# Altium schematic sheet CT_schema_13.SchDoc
size 519 x 434 mm
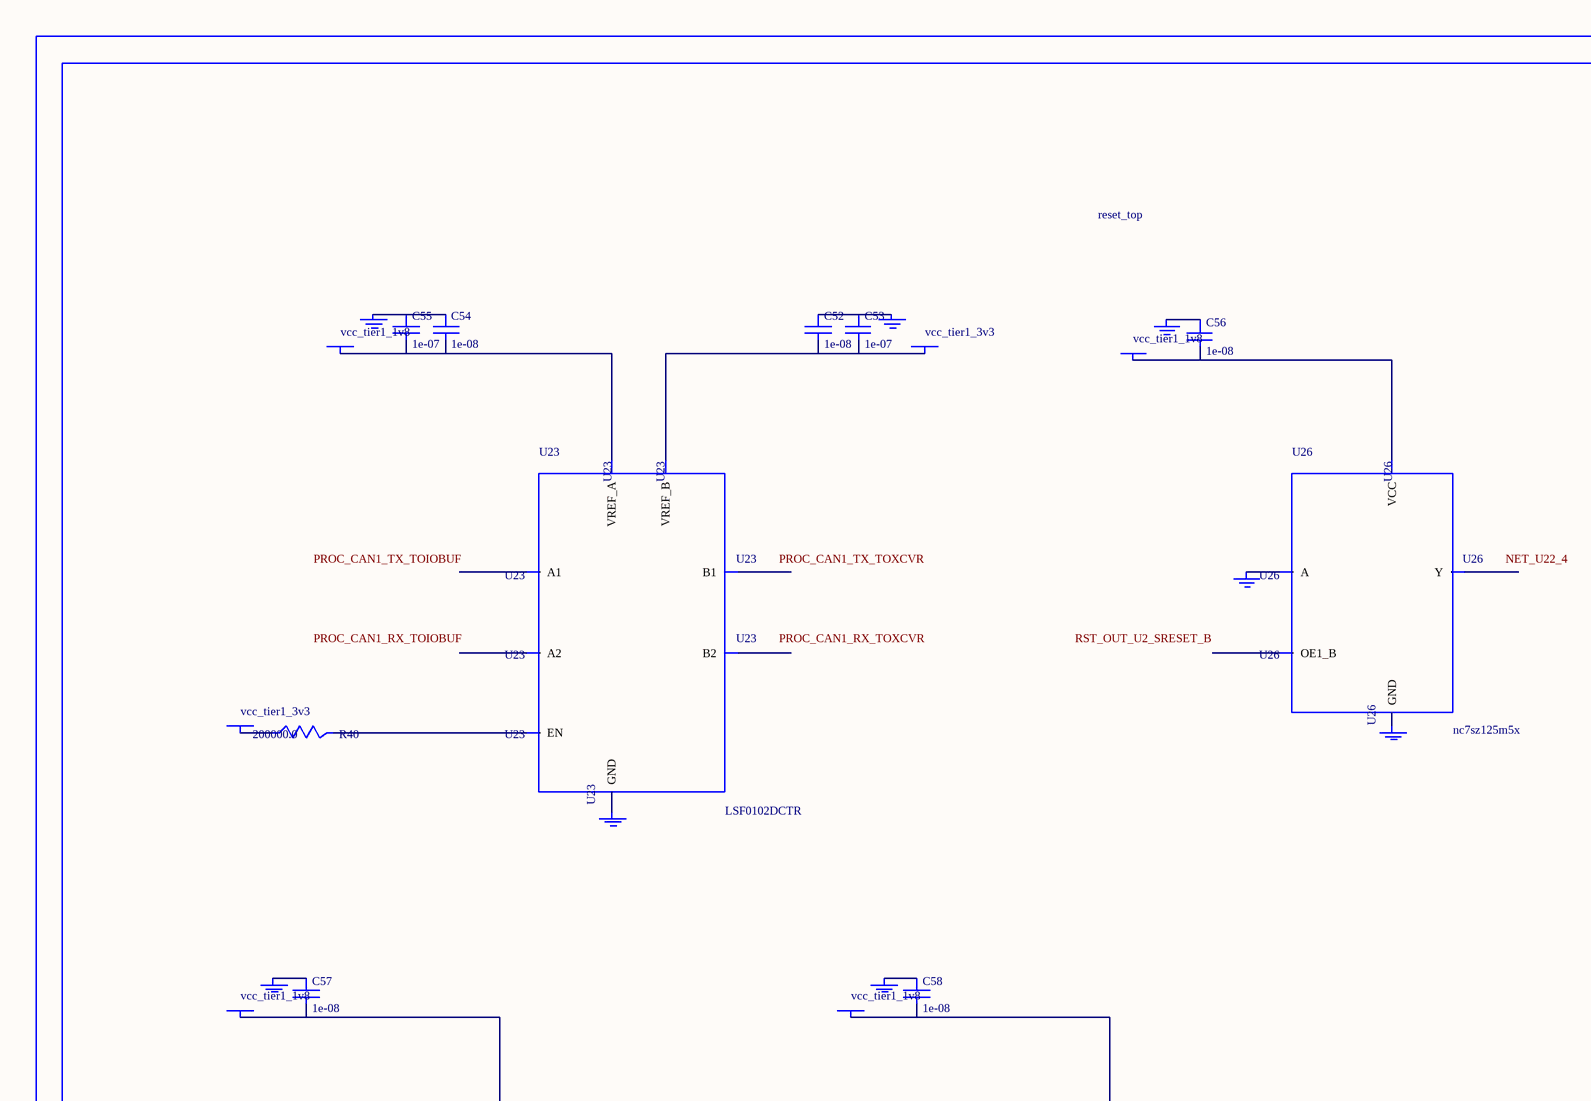
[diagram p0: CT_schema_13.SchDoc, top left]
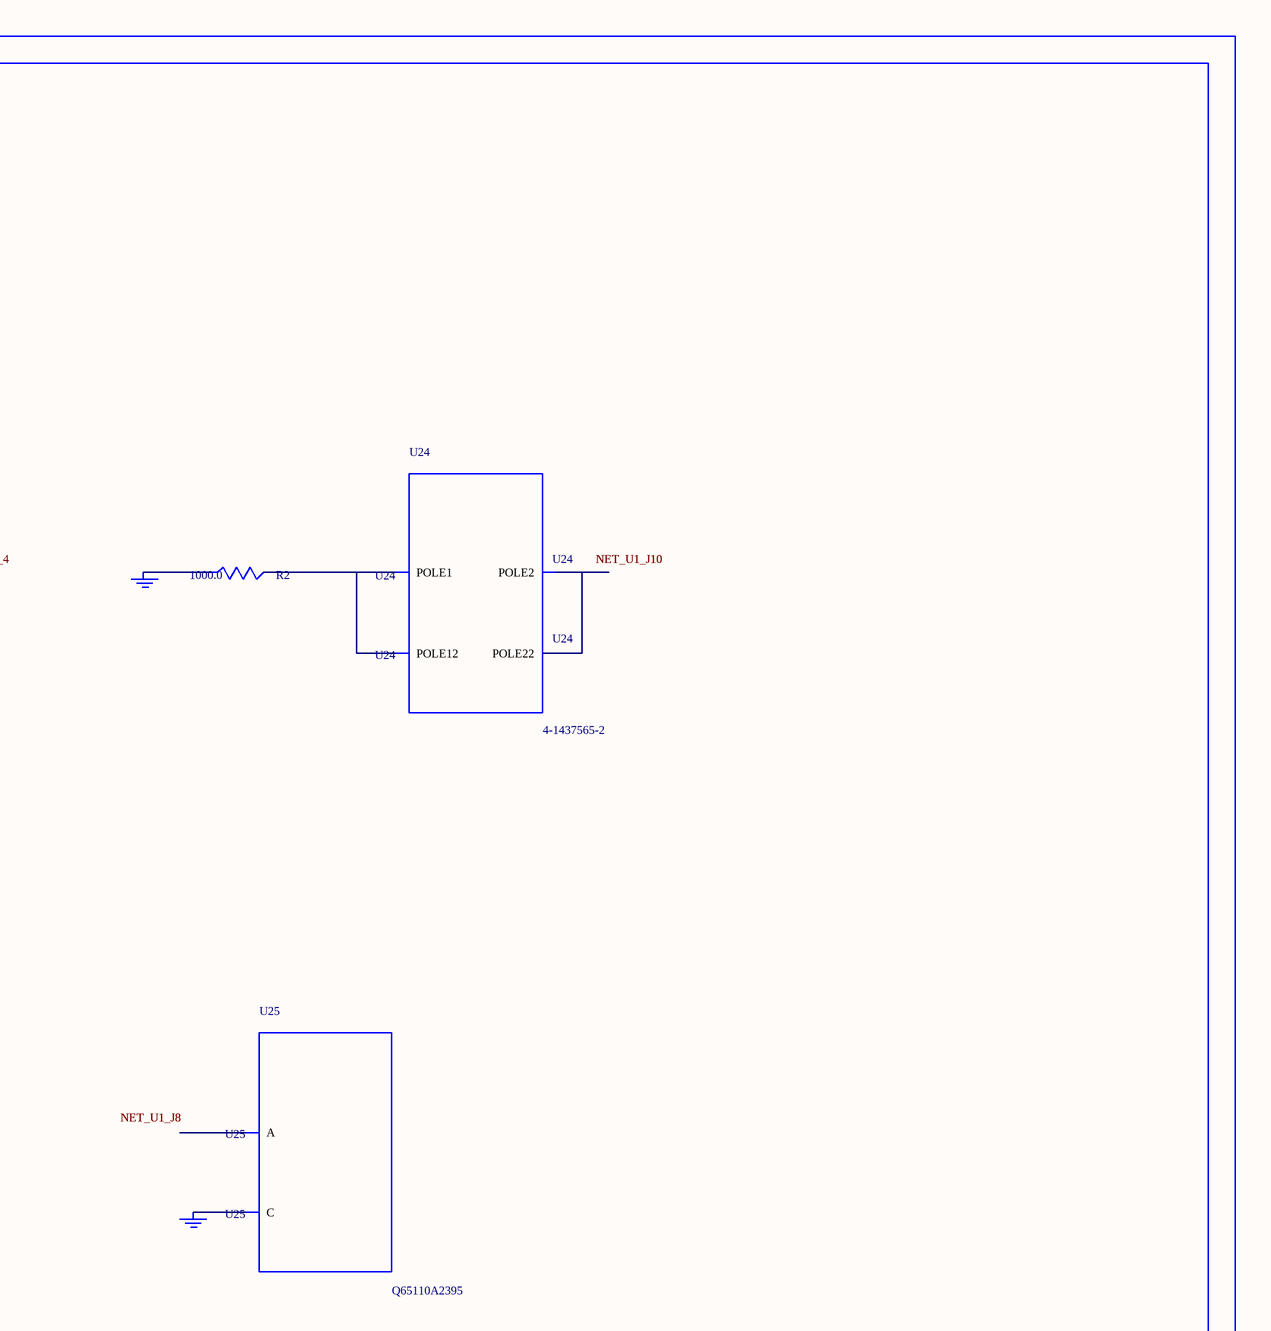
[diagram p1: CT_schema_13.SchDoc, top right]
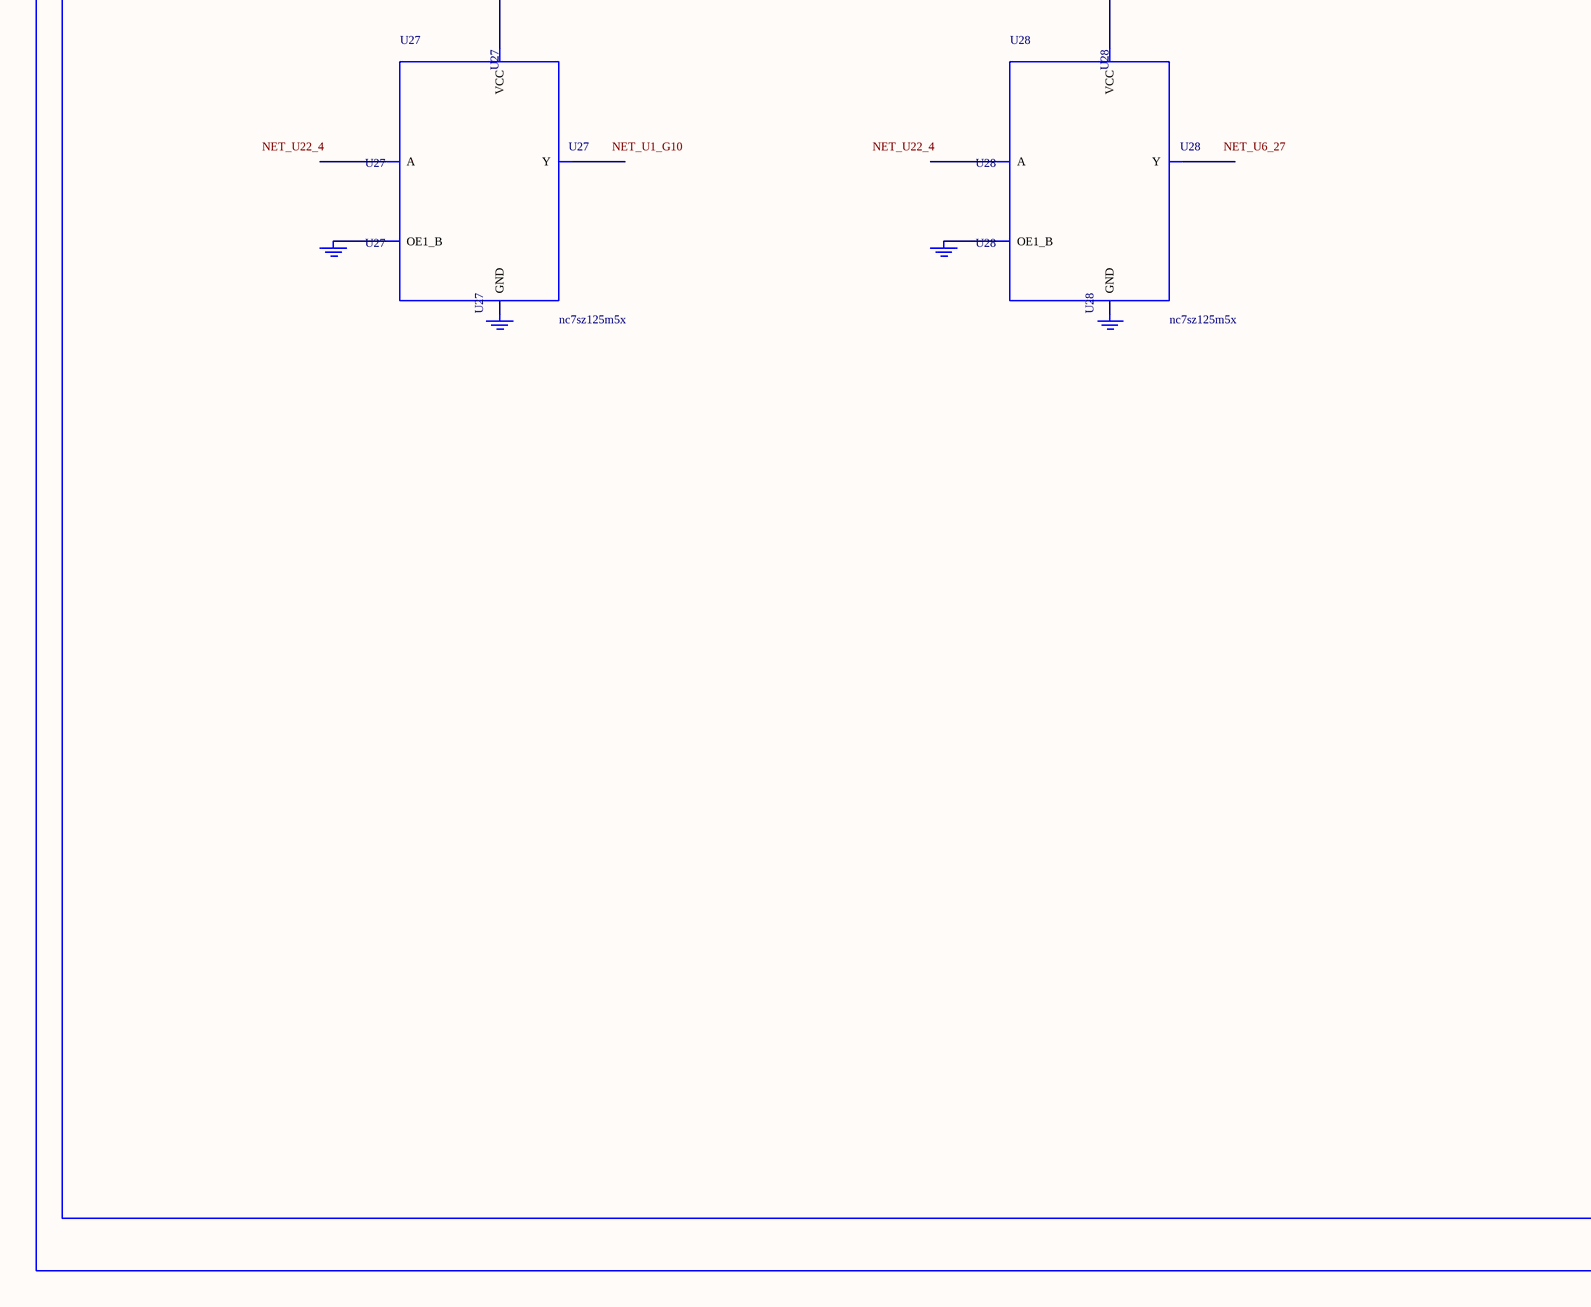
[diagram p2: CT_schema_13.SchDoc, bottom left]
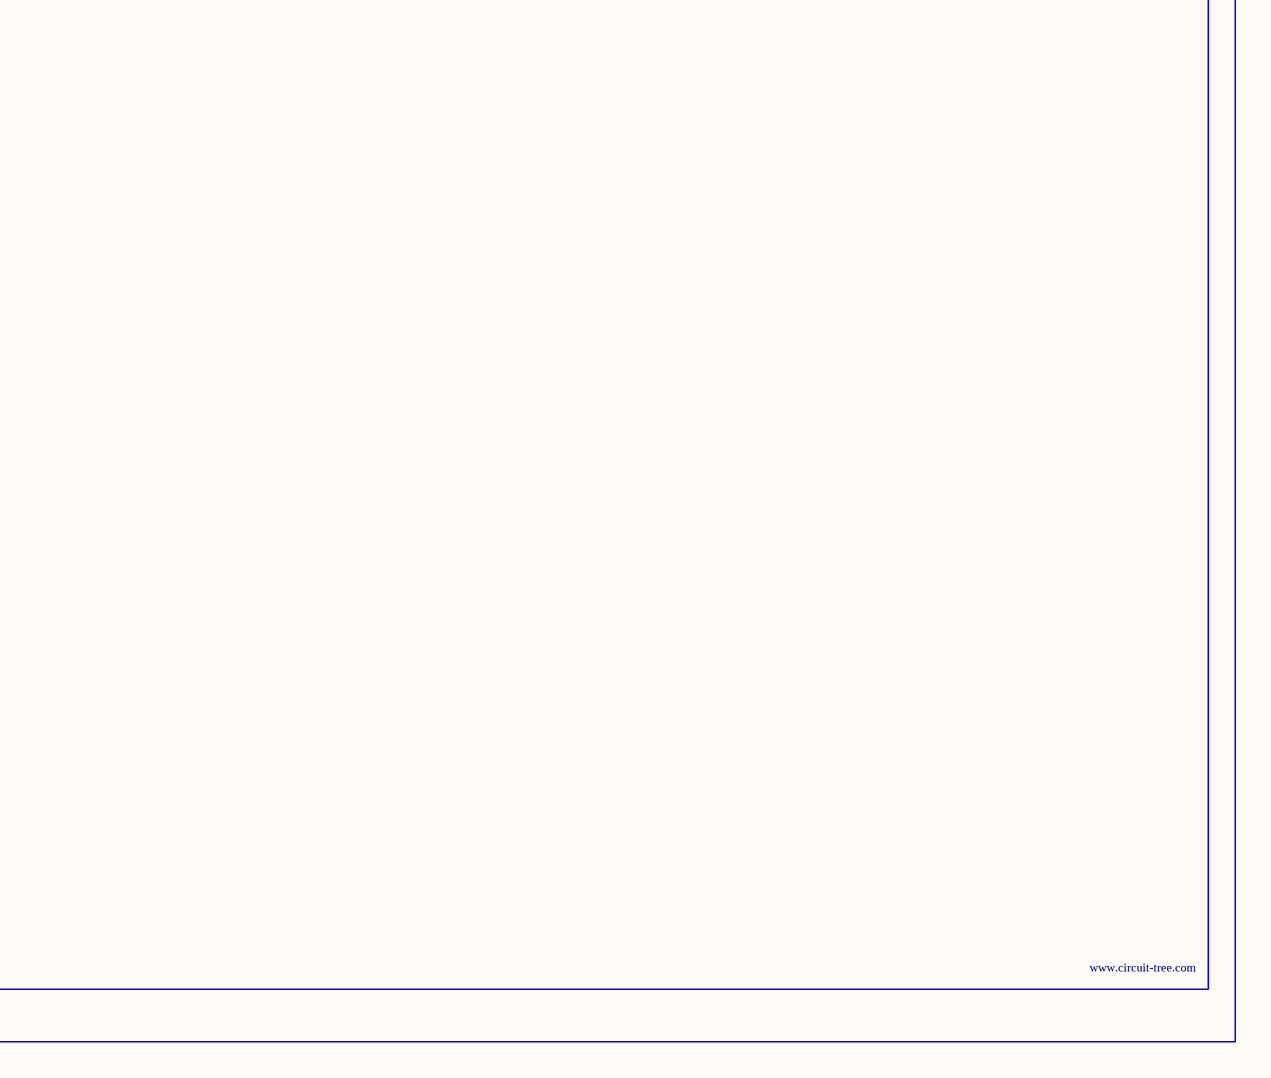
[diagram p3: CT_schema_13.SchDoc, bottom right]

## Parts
BORDER12  (no value)
C52  1e-08  [C0402]
C53  1e-07  [C0402]
C54  1e-08  [C0402]
C55  1e-07  [C0402]
C56  1e-08  [C0402]
C57  1e-08  [C0402]
C58  1e-08  [C0402]
GND_INSTANCE_12_0  (no value)
GND_INSTANCE_12_1  (no value)
GND_INSTANCE_12_2  (no value)
GND_INSTANCE_12_3  (no value)
GND_INSTANCE_12_4  (no value)
GND_INSTANCE_12_5  (no value)
GND_INSTANCE_12_6  (no value)
GND_INSTANCE_12_7  (no value)
GND_INSTANCE_12_8  (no value)
GND_INSTANCE_12_9  (no value)
GND_INSTANCE_12_10  (no value)
GND_INSTANCE_12_11  (no value)
GND_INSTANCE_12_12  (no value)
GND_INSTANCE_12_13  (no value)
POWER_INSTANCE_12_0  vcc_tier1_1v8
POWER_INSTANCE_12_1  vcc_tier1_3v3
POWER_INSTANCE_12_2  vcc_tier1_3v3
POWER_INSTANCE_12_3  vcc_tier1_1v8
POWER_INSTANCE_12_4  vcc_tier1_1v8
POWER_INSTANCE_12_5  vcc_tier1_1v8
R2  1000.0  [R0603]
R40  200000.0  [R0603]
U23  LSF0102DCTR  [DCU0008A_N]
U24  4-1437565-2  [SW_4-1437565-2]
U25  Q65110A2395  [LGM67K-G1J2-24-Z]
U26  nc7sz125m5x  [NC7SZ125M5X]
U27  nc7sz125m5x  [NC7SZ125M5X]
U28  nc7sz125m5x  [NC7SZ125M5X]

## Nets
NetC52_1: C52.1 C53.1 GND_INSTANCE_12_1.0(GND)
NetC52_2: C52.2 C53.2 POWER_INSTANCE_12_1.0(PWR) U23.7(VREF_B)
NetC54_1: C54.1 C55.1 GND_INSTANCE_12_0.0(GND)
NetC54_2: C54.2 C55.2 POWER_INSTANCE_12_0.0(PWR) U23.2(VREF_A)
NetC56_1: C56.1 GND_INSTANCE_12_5.0(GND)
NetC56_2: C56.2 POWER_INSTANCE_12_3.0(PWR) U26.5(VCC)
NetC57_1: C57.1 GND_INSTANCE_12_8.0(GND)
NetC57_2: C57.2 POWER_INSTANCE_12_4.0(PWR) U27.5(VCC)
NetC58_1: C58.1 GND_INSTANCE_12_11.0(GND)
NetC58_2: C58.2 POWER_INSTANCE_12_5.0(PWR) U28.5(VCC)
NetGND_INSTANCE_12_2_0: GND_INSTANCE_12_2.0(GND) U23.1(GND)
NetGND_INSTANCE_12_3_0: GND_INSTANCE_12_3.0(GND) R2.1
NetGND_INSTANCE_12_4_0: GND_INSTANCE_12_4.0(GND) U25.C
NetGND_INSTANCE_12_6_0: GND_INSTANCE_12_6.0(GND) U26.2(A)
NetGND_INSTANCE_12_7_0: GND_INSTANCE_12_7.0(GND) U26.3(GND)
NetGND_INSTANCE_12_9_0: GND_INSTANCE_12_9.0(GND) U27.1(OE1_B)
NetGND_INSTANCE_12_10_0: GND_INSTANCE_12_10.0(GND) U27.3(GND)
NetGND_INSTANCE_12_12_0: GND_INSTANCE_12_12.0(GND) U28.1(OE1_B)
NetGND_INSTANCE_12_13_0: GND_INSTANCE_12_13.0(GND) U28.3(GND)
NetPOWER_INSTANCE_12_2_0: POWER_INSTANCE_12_2.0(PWR) R40.1
NetR2_2: R2.2 U24.1(POLE1) U24.2(POLE12)
NetR40_2: R40.2 U23.8(EN)
NetU24_3: U24.3(POLE2) U24.4(POLE22)

Not connected (* = marked no-connect by the designer): U23 3(A1) 4(A2) 5(B2) 6(B1); U25 A; U26 1(OE1_B) 4(Y); U27 2(A) 4(Y); U28 2(A) 4(Y)

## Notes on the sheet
- Labels drawn without touching a wire or pin: NET_U1_G10, NET_U6_27, NET_U22_4, PROC_CAN1_RX_TOIOBUF, PROC_CAN1_RX_TOXCVR, PROC_CAN1_TX_TOIOBUF, PROC_CAN1_TX_TOXCVR, RST_OUT_U2_SRESET_B

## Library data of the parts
BORDER12 = BORDER_PAGE12
C52 C54 C56-C58 = C0402C103K3RAC
C53 C55 = C0402C104K3RACTU
GND_INSTANCE_12_0-GND_INSTANCE_12_13 = GND
POWER_INSTANCE_12_0-POWER_INSTANCE_12_5 = PWR
R2 = RC0603JR-071KL
R40 = RC0603JR-07200KL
